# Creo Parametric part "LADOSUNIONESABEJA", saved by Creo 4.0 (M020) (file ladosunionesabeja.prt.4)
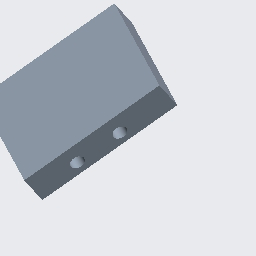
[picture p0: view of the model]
Units: millimeter Newton Second (mmNs); MM, TONNE, SECS

Created from: MMNS_PART_SOLID.PRT

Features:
  1. datum plane "RIGHT"
  2. datum plane "TOP"
  3. datum plane "FRONT"
  4. coordinate system
  5. sketch "Sketch 1"
  6. extrusion "Extrude 1"
  7. pattern "Pattern 1"
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
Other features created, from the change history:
  hole "Hole 1"
  hole "Hole 1 [2]"
  hole "Hole 1 [3]"
  hole "Hole 2"
  pattern "Patrón 2"
  hole "Taladro 2 [2]"

Surfaces: 11 plane, 5 cylinder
